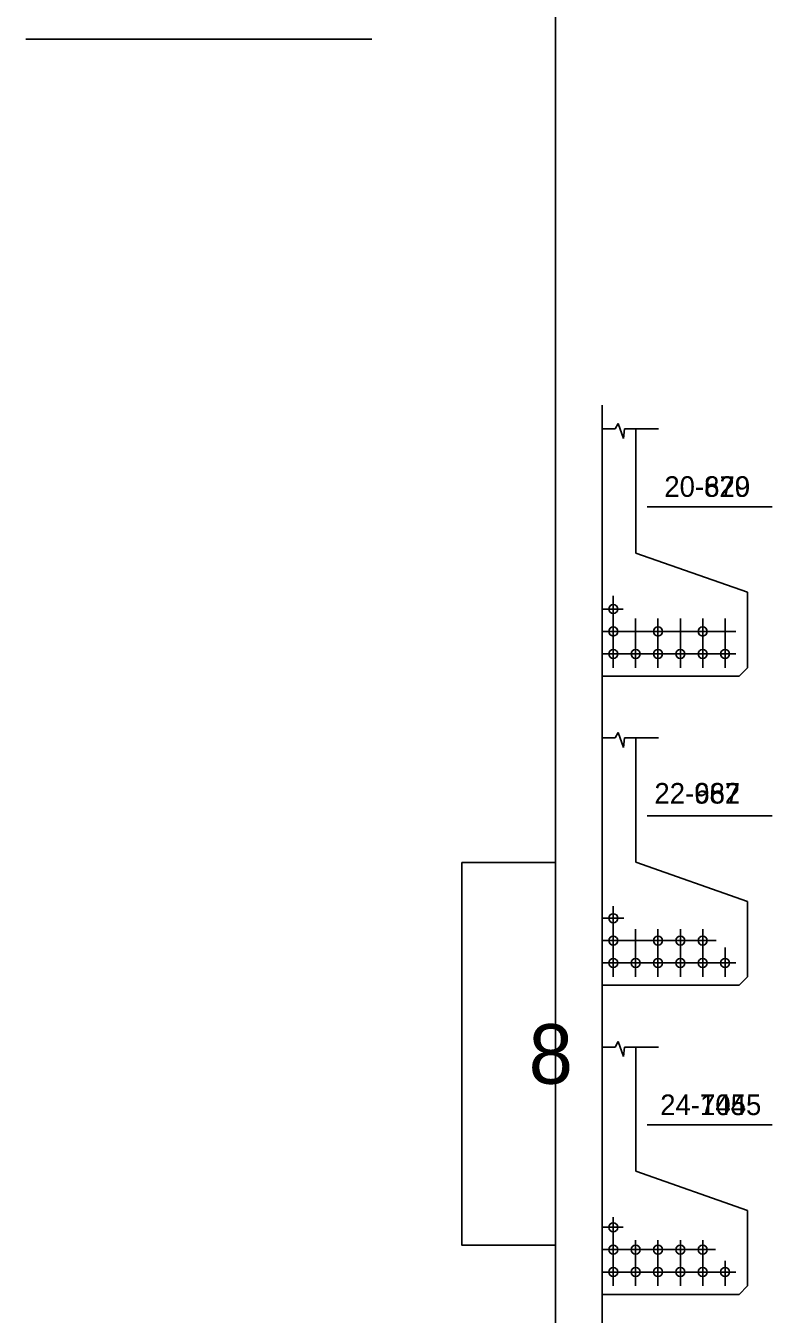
# Model space of a CAD drawing. Extents: x 1005 to 1133, y 2006 to 2074.
# Drawn here: x 1005.19 to 1017.27, y 2019.94 to 2040.78 of the extents above; entities that cross this region are included whole.
import ezdxf

# ---------------------------------------------------------------- set-up
doc = ezdxf.new("R2010")
doc.units = 0
for name, color, linetype in [('Level 1', 7, 'Continuous'), ('Level 37', 7, 'Continuous'), ('Level 8', 7, 'Continuous'), ('Level 9', 7, 'Continuous')]:
    doc.layers.add(name, color=color, linetype=linetype)

msp = doc.modelspace()

# ---------------------------------------------------------------- linework, layer by layer
at = {"layer": 'Level 1'}
msp.add_line((1013.763, 2012.562), (1013.763, 2068.561), dxfattribs=at)
msp.add_lwpolyline([(1013.763, 2027.241), (1012.249, 2027.241), (1012.249, 2021.051), (1013.763, 2021.051)], close=True, dxfattribs=at)
at = {"layer": 'Level 37'}
msp.add_line((1010.791, 2040.561), (1005.193, 2040.561), dxfattribs=at)
at = {"layer": 'Level 8'}
for p, q in [((1014.516, 2014.747), (1014.516, 2034.639)), ((1014.729, 2034.258), (1014.776, 2034.347)), ((1014.776, 2034.347), (1014.865, 2034.104)), ((1014.516, 2034.258), (1014.729, 2034.258)), ((1014.865, 2034.104), (1014.878, 2034.258)), ((1014.878, 2034.258), (1015.427, 2034.258)), ((1015.06, 2032.248), (1015.06, 2034.258)), ((1015.244, 2032.998), (1017.269, 2032.998)), ((1015.06, 2032.248), (1016.869, 2031.614)), ((1014.697, 2030.392), (1014.697, 2031.558)), ((1016.869, 2030.392), (1016.869, 2031.614)), ((1014.858, 2031.342), (1014.516, 2031.342)), ((1015.059, 2030.392), (1015.059, 2031.188)), ((1015.421, 2030.392), (1015.421, 2031.188)), ((1015.783, 2030.392), (1015.783, 2031.188)), ((1016.145, 2030.392), (1016.145, 2031.188)), ((1016.507, 2030.392), (1016.507, 2031.188)), ((1016.681, 2030.98), (1014.516, 2030.98)), ((1016.681, 2030.618), (1014.516, 2030.618)), ((1016.733, 2030.256), (1016.869, 2030.392)), ((1014.516, 2030.256), (1016.733, 2030.256)), ((1014.729, 2029.258), (1014.776, 2029.347)), ((1014.776, 2029.347), (1014.865, 2029.104)), ((1014.516, 2029.258), (1014.729, 2029.258)), ((1014.865, 2029.104), (1014.878, 2029.258)), ((1014.878, 2029.258), (1015.427, 2029.258)), ((1015.06, 2027.248), (1015.06, 2029.258)), ((1015.244, 2027.998), (1017.269, 2027.998)), ((1015.06, 2027.248), (1016.869, 2026.614)), ((1014.697, 2025.392), (1014.697, 2026.536)), ((1016.869, 2025.392), (1016.869, 2026.614)), ((1014.87, 2026.342), (1014.516, 2026.342)), ((1015.059, 2025.392), (1015.059, 2026.167)), ((1015.421, 2025.392), (1015.421, 2026.167)), ((1015.783, 2025.392), (1015.783, 2026.167)), ((1016.145, 2025.392), (1016.145, 2026.167)), ((1016.364, 2025.98), (1014.516, 2025.98)), ((1016.507, 2025.392), (1016.507, 2025.87)), ((1016.681, 2025.618), (1014.516, 2025.618)), ((1016.733, 2025.256), (1016.869, 2025.392)), ((1014.516, 2025.256), (1016.733, 2025.256)), ((1014.729, 2024.258), (1014.776, 2024.347)), ((1014.776, 2024.347), (1014.865, 2024.104)), ((1014.516, 2024.258), (1014.729, 2024.258)), ((1014.865, 2024.104), (1014.878, 2024.258)), ((1014.878, 2024.258), (1015.427, 2024.258)), ((1015.06, 2022.248), (1015.06, 2024.258)), ((1015.244, 2022.998), (1017.269, 2022.998)), ((1015.06, 2022.248), (1016.869, 2021.614)), ((1014.697, 2020.392), (1014.697, 2021.503)), ((1016.869, 2020.392), (1016.869, 2021.614)), ((1014.857, 2021.342), (1014.516, 2021.342)), ((1015.059, 2020.392), (1015.059, 2021.134)), ((1015.421, 2020.392), (1015.421, 2021.134)), ((1015.783, 2020.392), (1015.783, 2021.134)), ((1016.145, 2020.392), (1016.145, 2021.134)), ((1016.351, 2020.98), (1014.516, 2020.98)), ((1016.507, 2020.392), (1016.507, 2020.798)), ((1016.681, 2020.618), (1014.516, 2020.618)), ((1016.733, 2020.256), (1016.869, 2020.392)), ((1014.516, 2020.256), (1016.733, 2020.256))]:
    msp.add_line(p, q, dxfattribs=at)
for centre in [(1014.697, 2031.342), (1014.697, 2030.98), (1015.421, 2030.98), (1016.145, 2030.98), (1014.697, 2030.618), (1015.059, 2030.618), (1015.421, 2030.618), (1015.783, 2030.618), (1016.145, 2030.618), (1016.507, 2030.618), (1014.697, 2026.342), (1014.697, 2025.98), (1015.421, 2025.98), (1015.783, 2025.98), (1016.145, 2025.98), (1014.697, 2025.618), (1015.059, 2025.618), (1015.421, 2025.618), (1015.783, 2025.618), (1016.145, 2025.618), (1016.507, 2025.618), (1014.697, 2021.342), (1014.697, 2020.98), (1015.059, 2020.98), (1015.421, 2020.98), (1015.783, 2020.98), (1016.145, 2020.98), (1014.697, 2020.618), (1015.059, 2020.618), (1015.421, 2020.618), (1015.783, 2020.618), (1016.145, 2020.618), (1016.507, 2020.618)]:
    msp.add_circle(centre, 0.073, dxfattribs=at)
at = {"layer": 'Level 9'}
for p, q in [((1014.516, 2014.747), (1014.516, 2034.639)), ((1014.729, 2034.258), (1014.776, 2034.347)), ((1014.776, 2034.347), (1014.865, 2034.104)), ((1014.516, 2034.258), (1014.729, 2034.258)), ((1014.865, 2034.104), (1014.878, 2034.258)), ((1014.878, 2034.258), (1015.427, 2034.258)), ((1015.06, 2032.248), (1015.06, 2034.258)), ((1015.244, 2032.998), (1017.269, 2032.998)), ((1015.06, 2032.248), (1016.869, 2031.614)), ((1014.697, 2030.392), (1014.697, 2031.558)), ((1016.869, 2030.392), (1016.869, 2031.614)), ((1014.858, 2031.342), (1014.516, 2031.342)), ((1015.059, 2030.392), (1015.059, 2031.188)), ((1015.421, 2030.392), (1015.421, 2031.188)), ((1015.783, 2030.392), (1015.783, 2031.188)), ((1016.145, 2030.392), (1016.145, 2031.188)), ((1016.507, 2030.392), (1016.507, 2031.188)), ((1016.681, 2030.98), (1014.516, 2030.98)), ((1016.681, 2030.618), (1014.516, 2030.618)), ((1016.733, 2030.256), (1016.869, 2030.392)), ((1014.516, 2030.256), (1016.733, 2030.256)), ((1014.729, 2029.258), (1014.776, 2029.347)), ((1014.776, 2029.347), (1014.865, 2029.104)), ((1014.516, 2029.258), (1014.729, 2029.258)), ((1014.865, 2029.104), (1014.878, 2029.258)), ((1014.878, 2029.258), (1015.427, 2029.258)), ((1015.06, 2027.248), (1015.06, 2029.258)), ((1015.244, 2027.998), (1017.269, 2027.998)), ((1015.06, 2027.248), (1016.869, 2026.614)), ((1014.697, 2025.392), (1014.697, 2026.536)), ((1016.869, 2025.392), (1016.869, 2026.614)), ((1014.87, 2026.342), (1014.516, 2026.342)), ((1015.059, 2025.392), (1015.059, 2026.167)), ((1015.421, 2025.392), (1015.421, 2026.167)), ((1015.783, 2025.392), (1015.783, 2026.167)), ((1016.145, 2025.392), (1016.145, 2026.167)), ((1016.364, 2025.98), (1014.516, 2025.98)), ((1016.507, 2025.392), (1016.507, 2025.87)), ((1016.681, 2025.618), (1014.516, 2025.618)), ((1016.733, 2025.256), (1016.869, 2025.392)), ((1014.516, 2025.256), (1016.733, 2025.256)), ((1014.729, 2024.258), (1014.776, 2024.347)), ((1014.776, 2024.347), (1014.865, 2024.104)), ((1014.516, 2024.258), (1014.729, 2024.258)), ((1014.865, 2024.104), (1014.878, 2024.258)), ((1014.878, 2024.258), (1015.427, 2024.258)), ((1015.06, 2022.248), (1015.06, 2024.258)), ((1015.244, 2022.998), (1017.269, 2022.998)), ((1015.06, 2022.248), (1016.869, 2021.614)), ((1014.697, 2020.392), (1014.697, 2021.503)), ((1016.869, 2020.392), (1016.869, 2021.614)), ((1014.857, 2021.342), (1014.516, 2021.342)), ((1015.059, 2020.392), (1015.059, 2021.134)), ((1015.421, 2020.392), (1015.421, 2021.134)), ((1015.783, 2020.392), (1015.783, 2021.134)), ((1016.145, 2020.392), (1016.145, 2021.134)), ((1016.351, 2020.98), (1014.516, 2020.98)), ((1016.507, 2020.392), (1016.507, 2020.798)), ((1016.681, 2020.618), (1014.516, 2020.618)), ((1016.733, 2020.256), (1016.869, 2020.392)), ((1014.516, 2020.256), (1016.733, 2020.256))]:
    msp.add_line(p, q, dxfattribs=at)
for centre in [(1014.697, 2031.342), (1014.697, 2030.98), (1015.421, 2030.98), (1016.145, 2030.98), (1014.697, 2030.618), (1015.059, 2030.618), (1015.421, 2030.618), (1015.783, 2030.618), (1016.145, 2030.618), (1016.507, 2030.618), (1014.697, 2026.342), (1014.697, 2025.98), (1015.421, 2025.98), (1015.783, 2025.98), (1016.145, 2025.98), (1014.697, 2025.618), (1015.059, 2025.618), (1015.421, 2025.618), (1015.783, 2025.618), (1016.145, 2025.618), (1016.507, 2025.618), (1014.697, 2021.342), (1014.697, 2020.98), (1015.059, 2020.98), (1015.421, 2020.98), (1015.783, 2020.98), (1016.145, 2020.98), (1014.697, 2020.618), (1015.059, 2020.618), (1015.421, 2020.618), (1015.783, 2020.618), (1016.145, 2020.618), (1016.507, 2020.618)]:
    msp.add_circle(centre, 0.073, dxfattribs=at)

# ---------------------------------------------------------------- texts
at = {"layer": 'Level 1'}
msp.add_text('8', height=0.963, dxfattribs=at).set_placement((1013.329, 2023.664))
at = {"layer": 'Level 8'}
for s, p in [('20-620', (1015.523, 2033.158)), ('22-682', (1015.363, 2028.196)), ('24-744', (1015.457, 2023.157))]:
    msp.add_text(s, height=0.3333, dxfattribs=at).set_placement(p)
at = {"layer": 'Level 9'}
for s, p in [('20-879', (1015.523, 2033.158)), ('22-967', (1015.363, 2028.196)), ('24-1055', (1015.457, 2023.157))]:
    msp.add_text(s, height=0.3333, dxfattribs=at).set_placement(p)

doc.saveas('drawing.dxf')
